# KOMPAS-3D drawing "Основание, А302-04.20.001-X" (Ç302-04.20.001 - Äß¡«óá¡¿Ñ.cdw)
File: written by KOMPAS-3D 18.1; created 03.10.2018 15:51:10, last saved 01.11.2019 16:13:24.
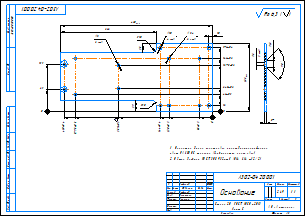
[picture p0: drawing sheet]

Sheet 1: A3, landscape

Document properties: Автор: Милов; Масса: 2.48623; Параметр неуказанной шероховатости: Ra 6,3; Полное имя файла: ..\3Д ПВХ\А302-01.20.001 - Основание.m3d; Организация: Милов

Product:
- Part/product: Основание  | designation А302-04.20.001-X
    Материал: Сталь 20  ГОСТ 1050-2013 (density 7820 kg/m3)
    Масса: 2.48623
    Раздел спецификации: Детали
    Форматы листов документа: A3
    source file: А302-04.20.001 - Основание.cdw
- Part/product: Основание  | designation А302-04.20.001
    Материал: Сталь 20  ГОСТ 1050-2013 (density 7820 kg/m3)
    Масса: 2.48623
    Раздел спецификации: Детали
    Форматы листов документа: A3
- Part/product: Основание  | designation А302-01.20.001
    Материал: Сталь 20  ГОСТ 1050-2013 (density 7820 kg/m3)
    Масса: 2.48169
    Раздел спецификации: Детали
    Форматы листов документа: A3
    source file: ..\3Д ПВХ\А302-01.20.001 - Основание.cdw, А302-04.20.001 - Основание.cdw

Title block, sheet 1: Наименование: Основание; designation: А302-04.20.001; Материал: Сталь 20  ГОСТ 1050-2013 / Лист 5; Масса: 2,49; scale: 1:1; Количество листов документа: 1; organisation: АО «Астерион»; Форматы листов документа: A3; stored path: \\192.168.87.28\Konstructor_doc\Мембранные насосы\Мембранный электропривод\А302-00.00.000 - ASTRA-302 (МЭ200)\3Д ПВХ\А302-00.20.001 - Основание.cdw; Разработал: Лифлянд; Проверил: Борисенко; Т. контр.: Лучихин

Views: Вид 1, Сзади, Проекционный вид 2, Местный разрез 1
Referenced files in \\192.168.87.28\Konstructor_doc\Мембранные насосы\Мембранный электропривод\А302-00.00.000 - ASTRA-302 (МЭ200)\3Д ПВХ\: А302-01.20.001 - Основание.m3d
Referenced files in D:\Мембранные насосы\Мембранный электропривод\А302-00.00.000 - ASTRA-302 (МЭ200)\3Д ПВХ\: А302-01.20.001 - Основание.m3d
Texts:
  Ra 6,3
  Ra 6,3 ( )
Dimensions and other numbers on the sheet: 35±0,2; 120±0,2; 259±0,2; 379,5±0,3; 410±0,4; 10; 144±0,4; 16; 46±0,3; 146±0,2; 176±0,4; 61; 131; 64,5±0,2; 127,5±0,2; 4 отв.; 8,4; 6 отв.; 8; 2 отв.; 188; 29; 25; 266; 420; 1; 4; 5; 18; 1:1; 2,49; 01.11.2019

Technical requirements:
  Покрытие: Эмаль порошковая эпоксидно-полиэфирная,
  цвет RAL5005, шагрень (допускается глянцевая).
  Общие допуски ГОСТ 30893.2-mK (H14, h14,  t2/2).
